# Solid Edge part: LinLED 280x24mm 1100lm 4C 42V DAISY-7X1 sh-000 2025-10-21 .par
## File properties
Author: patryk.ciesielski
Template: iso metric part.par
Last saved by: patryk.ciesielski
Revision: 2
Application: Solid Edge
Gęstość: 0.000 kg/m^3
Dokładność: 0.990
Username: patryk.ciesielski
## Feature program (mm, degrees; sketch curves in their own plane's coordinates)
body "unnamed Body 1"
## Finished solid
Body 1: solid body, 1664 faces, 4948 edges, 3414 vertices.
  Faces by surface: plane 1194, cylinder 412, swept 28, sphere 18, cone 4, spline 4, torus 4
  Edges by curve: line 3680, circle 770, curve on surface 344, ellipse 154
Bounding box of the edges (mm; curved faces can reach further): 279.000 x 24.000 x 4.330, from (-139.5, -12, 0) to (139.5, 12, 4.33).
Cylindrical faces by radius (mm): R0.0495 x4, R0.0647 x8, R0.0649 x8, R0.1 x148, R0.1164 x4, R0.1314 x16, R0.1729 x4, R0.2 x112, R0.2289 x4, R0.47 x8, R0.5 x56, R0.6 x4, R0.625 x4, R0.75 x8, R1 x10, R1.0277 x4, R1.05 x4, R1.7 x6
Conical faces (half-angle, radius in mm at the cone's reference point): 36.872 deg R0.8536 x4
Toroidal faces (ring radius, tube radius in mm): R1.2 r0.1 x4
Spherical faces by radius (mm): R0.1 x10, R0.5 x8
Planar faces by outward normal: +x 73, +y 105, +z 169, -x 121, -y 105, -z 29, oblique 592
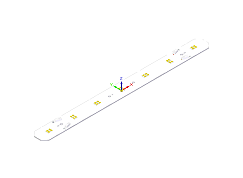
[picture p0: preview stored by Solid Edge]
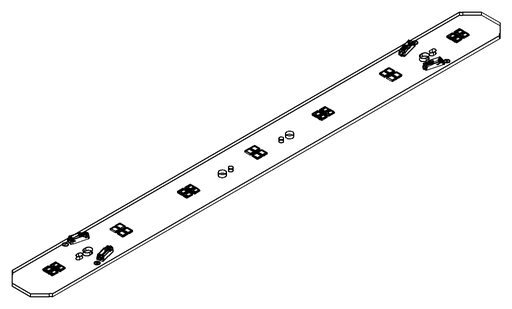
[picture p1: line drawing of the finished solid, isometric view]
